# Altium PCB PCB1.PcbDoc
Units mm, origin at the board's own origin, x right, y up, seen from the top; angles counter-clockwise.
Board outline 116 x 60 mm, 4 copper layers (Top Layer, Inner up, Inner bottom, Bottom Layer), stack 0.602 mm thick; 2 components, 4 nets, 12 pads, 256 vias.
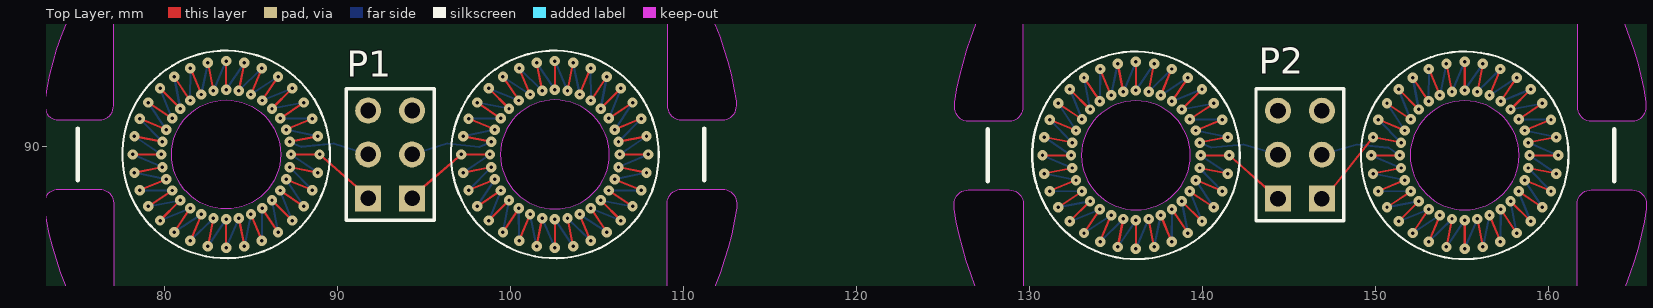
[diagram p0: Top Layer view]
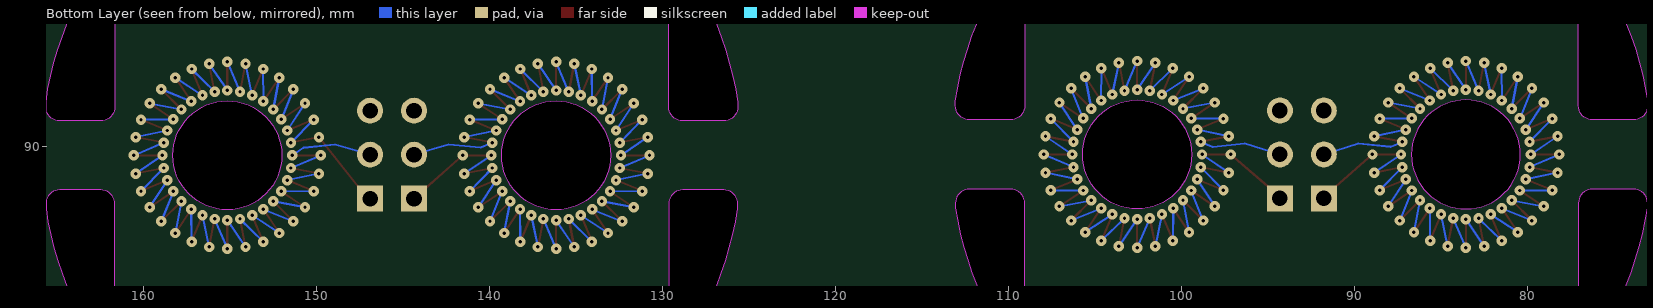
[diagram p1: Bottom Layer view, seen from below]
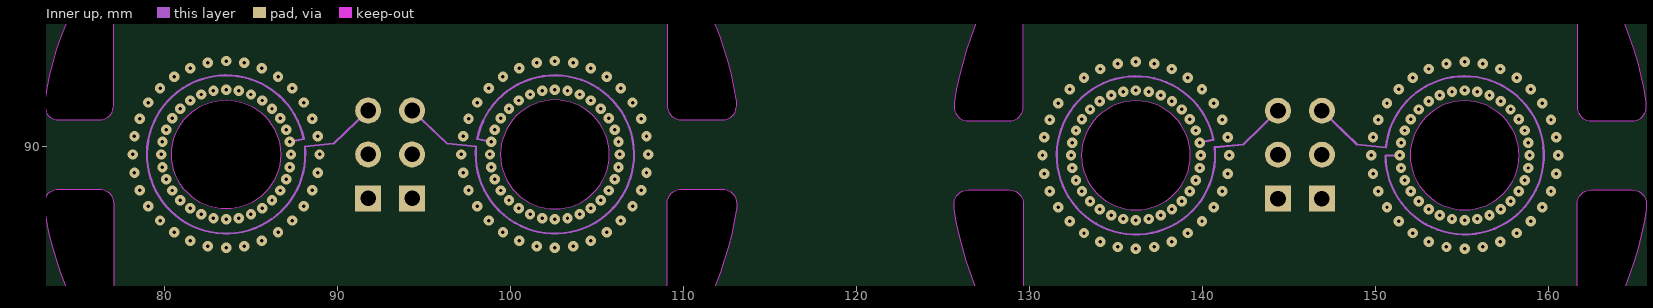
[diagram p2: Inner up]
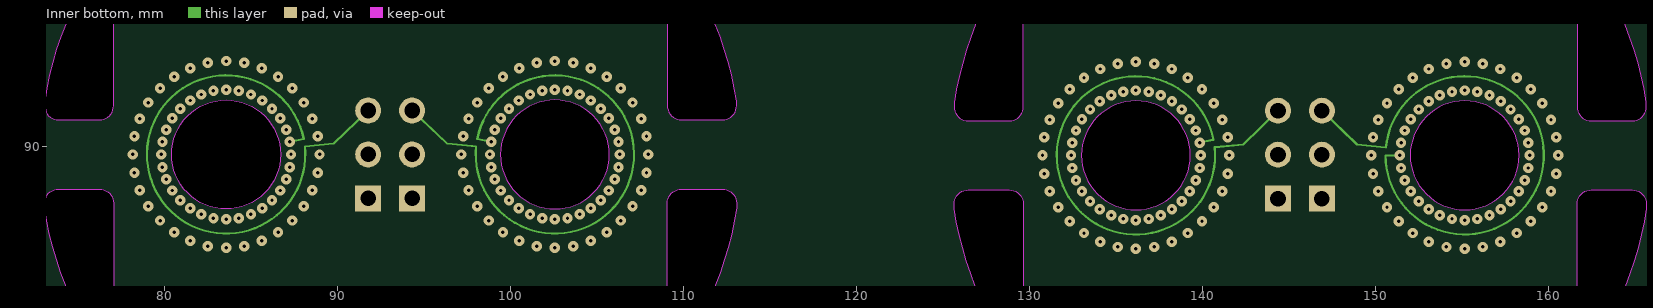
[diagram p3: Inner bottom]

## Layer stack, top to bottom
Top Solder: solder mask 0.0102, Solder Resist, Dk 3.5
Top Layer: signal copper 0.035
Dielectric 2: prepreg 0.0711, PP-006, Dk 4.1
Inner up: signal copper 0.035
Dielectric 1: dielectric 0.32, FR-4, Dk 4.8
Inner bottom: signal copper 0.035
Dielectric 3: prepreg 0.0711, PP-006, Dk 4.1
Bottom Layer: signal copper 0.035
Bottom Solder: solder mask 0.0102, Solder Resist, Dk 3.5

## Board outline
62,59 62,119 178,119 178,59
cut-out: 77.084,80.776 ccw(c93.084,89.555) 91.334,71.389 91.334,72.742 cw(c92.147,72.742) 92.147,73.555 94.021,73.555 cw(c94.021,72.742) 94.834,72.742 94.834,71.389 ccw(c93.084,89.555) 109.084,80.776 109.084,86.742 cw(c109.897,86.742) 109.897,87.555 112.275,87.555 cw(c112.275,86.742) 113.088,86.742 113.088,86.476 cw(c93.084,89.555) 73.08,86.482 73.08,86.742 cw(c73.893,86.742) 73.893,87.555 76.271,87.555 cw(c76.271,86.742) 77.084,86.742
cut-out: 73.078,92.368 ccw(c73.89,92.368) 73.89,91.555 76.271,91.555 ccw(c76.271,92.368) 77.084,92.368 77.084,98.334 cw(c93.084,89.555) 91.334,107.721 91.334,106.368 ccw(c92.147,106.368) 92.147,105.555 94.021,105.555 ccw(c94.021,106.368) 94.834,106.368 94.834,107.721 cw(c93.084,89.555) 109.084,98.334 109.084,92.368 ccw(c109.897,92.368) 109.897,91.555 112.276,91.555 ccw(c112.276,92.368) 113.089,92.368 113.089,92.629 ccw(c93.084,89.555) 73.078,92.614
cut-out: 125.661,92.317 ccw(c126.474,92.317) 126.474,91.504 128.855,91.504 ccw(c128.855,92.317) 129.667,92.317 129.667,98.283 cw(c145.667,89.504) 143.917,107.67 143.917,106.317 ccw(c144.73,106.317) 144.73,105.504 146.605,105.504 ccw(c146.605,106.317) 147.417,106.317 147.417,107.67 cw(c145.667,89.504) 161.667,98.283 161.667,92.317 ccw(c162.48,92.317) 162.48,91.504 164.859,91.504 ccw(c164.859,92.317) 165.672,92.317 165.672,92.578 ccw(c145.667,89.504) 125.661,92.564
cut-out: 129.667,80.726 ccw(c145.667,89.504) 143.917,71.338 143.917,72.691 cw(c144.73,72.691) 144.73,73.504 146.605,73.504 cw(c146.605,72.691) 147.417,72.691 147.417,71.338 ccw(c145.667,89.504) 161.667,80.726 161.667,86.691 cw(c162.48,86.691) 162.48,87.504 164.858,87.504 cw(c164.858,86.691) 165.671,86.691 165.671,86.426 cw(c145.667,89.504) 125.663,86.431 125.663,86.691 cw(c126.476,86.691) 126.476,87.504 128.855,87.504 cw(c128.855,86.691) 129.667,86.691
cut-out: 83.584,86.405 cw(c83.584,89.555) 80.434,89.555 cw(c83.584,89.555) 83.584,92.705 cw(c83.584,89.555) 86.734,89.555 cw(c83.584,89.555)
cut-out: 99.434,89.555 ccw(c102.584,89.555) 102.584,86.405 ccw(c102.584,89.555) 105.734,89.555 ccw(c102.584,89.555) 102.584,92.705 ccw(c102.584,89.555)
cut-out: 133.017,89.504 ccw(c136.167,89.504) 136.167,86.354 ccw(c136.167,89.504) 139.317,89.504 ccw(c136.167,89.504) 136.167,92.654 ccw(c136.167,89.504)
cut-out: 152.017,89.504 ccw(c155.167,89.504) 155.167,86.354 ccw(c155.167,89.504) 158.317,89.504 ccw(c155.167,89.504) 155.167,92.654 ccw(c155.167,89.504)

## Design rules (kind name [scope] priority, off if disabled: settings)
BoardOutlineClearance [All] p1: gap=0.2 ignorepadtopadclearanceinfootprint=FALSE
Clearance [All] p1: gap=0.102 ignorepadtopadclearanceinfootprint=FALSE except(0.127: Arc-Via Track-Via SMDPad-Via THPad-Via Via-Via Via-Fill Via-Poly Via-Region Via-Text; 0.25: Arc-Hole Track-Hole SMDPad-Hole THPad-Hole Via-Hole Fill-Hole Poly-Hole Region-Hole Text-Hole)
ComponentClearance [All] p1: gap=0.102 collisioncheckmode=3 verticalgap=0.102 showdistances=TRUE
DiffPairsRouting [All] p1: maxlimit=0.102 minlimit=0.102 mostfreqgap=0.102 toplayer_minwidth=0.102 toplayer_maxwidth=1816.048 toplayer_prefwidth=0.102 midlayer1_minwidth=0.102 midlayer1_maxwidth=1816.048 midlayer1_prefwidth=0.102 midlayer2_minwidth=0.102 midlayer2_maxwidth=1816.048 midlayer2_prefwidth=0.102 bottomlayer_minwidth=0.102 bottomlayer_maxwidth=1816.048 bottomlayer_prefwidth=0.102 maxuncoupledlength=12.7
Height [All] p1: minheight=0 maxheight=1816.048 prefheight=12.7
HoleSize [All] p1: absolutevalues=TRUE maxlimit=6.3 minlimit=0.2 maxpercent=80.000 minpercent=20.000
HoleToHoleClearance [All] p1: gap=0.25 allowstackedmicrovias=FALSE
MinimumAnnularRing [All] p1: minimumring=0.076
MinimumSolderMaskSliver [All] p1: minsoldermaskwidth=0
PlaneClearance [All] p1: clearance=0.102
PlaneConnect PlaneConnectPowerPads [InPadClass('PowerPads')] p1: planeconnectstyle=Direct reliefexpansion=0.508 reliefentries=4 reliefconductorwidth=0.254 reliefairgap=0.254
PlaneConnect [All] p2: pad.planeconnectstyle=Relief pad.reliefexpansion=0.3 pad.reliefentries=4 pad.reliefconductorwidth=0.102 pad.reliefairgap=0.102 via.planeconnectstyle=Direct via.reliefexpansion=0.3 via.reliefentries=4 via.reliefconductorwidth=0.127 via.reliefairgap=0.127
PolygonConnect PolygonConnectPowerPads [All vs (InPadClass('PowerPads'))] p1: connectstyle=Direct reliefconductorwidth=0.254 reliefentries=4 polygonreliefangle="90 Angle" airgapwidth=0.254
PolygonConnect [All] p2: thpad.connectstyle=Relief thpad.reliefconductorwidth=0.102 thpad.reliefentries=4 thpad.polygonreliefangle="90 Angle" thpad.airgapwidth=0.102 smdpad.connectstyle=Relief smdpad.reliefconductorwidth=0.102 smdpad.reliefentries=4 smdpad.polygonreliefangle="90 Angle" smdpad.airgapwidth=0.102 via.connectstyle=Direct via.reliefconductorwidth=0.127 via.reliefentries=4 via.polygonreliefangle="90 Angle" via.airgapwidth=0.127
RoutingVias [All] p1: holewidth=0.2 width=0.45 viastyle="Through Hole" minholewidth=0.2 minwidth=0.45 maxholewidth=6.3 maxwidth=6.55
SilkToSilkClearance [All] p1: silktosilkclearance=0
SilkToSolderMaskClearance [IsPad] p1: minsilkscreentomaskgap=0.102 clearancetoexposedcopper=TRUE
SolderMaskExpansion [All] p1: expansion=0.075 istentingtop=FALSE
Width [All] p1: maxlimit=1816.048 minlimit=0.102 preferedwidth=0.102
20 further rules are at their usual default settings.

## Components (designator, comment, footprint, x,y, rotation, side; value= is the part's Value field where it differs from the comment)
P1 "Header 3X2A" HDR2X3_CEN 94.334,87.015 r90 top
P2 "Header 3X2A" HDR2X3_CEN 146.917,87.004 r90 top

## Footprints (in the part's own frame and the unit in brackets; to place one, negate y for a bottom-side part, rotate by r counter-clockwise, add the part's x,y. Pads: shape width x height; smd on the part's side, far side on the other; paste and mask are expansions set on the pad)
HDR2X3_CEN [mm] "Connector; Header; 3x2 Position"
  rect 1.5x1.5 hole 0.9: 1(0,0) 4(0,2.54)
  round 1.5 hole 0.9: 2(2.54,0) 3(5.08,0) 5(2.54,2.54) 6(5.08,2.54)
  silkscreen extent -1.27,-1.27 6.35,3.81

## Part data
P1 P2: "Header, 3-Pin, Dual row"

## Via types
v1: diameter 0.6, hole 0.2, Top Layer to Bottom Layer, 256 vias

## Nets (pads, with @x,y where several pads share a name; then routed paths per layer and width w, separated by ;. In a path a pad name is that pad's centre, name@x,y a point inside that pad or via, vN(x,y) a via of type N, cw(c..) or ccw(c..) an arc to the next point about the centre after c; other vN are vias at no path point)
coil1: P2.1 P2.2 P2.3 | length 187.4
  Top Layer w0.125: P2.1 147.605,87.692 v1(149.871,90.558) v1(151.489,90.236) ; v1(149.767,89.504) v1(151.417,89.504) ; v1(149.871,88.451) v1(151.489,88.773) ; v1(150.178,87.438) v1(151.703,88.069) ; v1(150.178,91.571) v1(151.703,90.939) ; v1(150.677,86.504) v1(152.049,87.421) ; v1(150.677,92.504) v1(152.049,91.588) ; v1(151.349,85.686) v1(152.516,86.853) ; v1(151.349,93.323) v1(152.516,92.156) ; v1(152.167,85.014) v1(153.084,86.386) ; v1(152.167,93.994) v1(153.084,92.622) ; v1(153.101,84.515) v1(153.732,86.04) ; v1(153.101,94.493) v1(153.732,92.969) ; v1(154.114,84.208) v1(154.436,85.826) ; v1(154.114,94.8) v1(154.436,93.182) ; v1(155.167,84.104) v1(155.167,85.754) ; v1(155.167,93.254) v1(155.167,94.904) ; v1(155.899,85.826) v1(156.221,84.208) ; v1(155.899,93.182) v1(156.221,94.8) ; v1(156.602,86.04) v1(157.234,84.515) ; v1(156.602,92.969) v1(157.234,94.493) ; v1(157.251,86.386) v1(158.167,85.014) ; v1(157.251,92.622) v1(158.167,93.994) ; v1(157.819,86.853) v1(158.986,85.686) ; v1(157.819,92.156) v1(158.986,93.323) ; v1(158.285,87.421) v1(159.657,86.504) ; v1(158.285,91.588) v1(159.657,92.504) ; v1(158.632,88.069) v1(160.156,87.438) ; v1(158.632,90.939) v1(160.156,91.571) ; v1(158.845,88.773) v1(160.464,88.451) ; v1(158.845,90.236) v1(160.464,90.558) ; v1(158.917,89.504) v1(160.567,89.504)
  Inner up w0.125: P2.3 148.942,90.129 150.615,89.961 cw(c155.167,89.504) 150.592,89.504 v1(151.417,89.504)
  Inner bottom w0.125: P2.3 148.942,90.129 150.615,89.961 cw(c155.167,89.504) 150.592,89.504 v1(151.417,89.504)
  Bottom Layer w0.125: P2.2 148.942,90.129 150.769,89.946 v1(151.417,89.504) ; v1(149.767,89.504) v1(151.489,88.773) ; v1(149.871,88.451) v1(151.703,88.069) ; v1(150.178,87.438) v1(152.049,87.421) ; v1(150.178,91.571) v1(151.489,90.236) ; v1(150.677,86.504) v1(152.516,86.853) ; v1(150.677,92.504) v1(151.703,90.939) ; v1(151.349,85.686) v1(153.084,86.386) ; v1(151.349,93.323) v1(152.049,91.588) ; v1(152.167,85.014) v1(153.732,86.04) ; v1(152.167,93.994) v1(152.516,92.156) ; v1(153.084,92.622) v1(153.101,94.493) ; v1(153.101,84.515) v1(154.436,85.826) ; v1(153.732,92.969) v1(154.114,94.8) ; v1(154.114,84.208) v1(155.167,85.754) ; v1(154.436,93.182) v1(155.167,94.904) ; v1(155.167,84.104) v1(155.899,85.826) ; v1(155.167,93.254) v1(156.221,94.8) ; v1(155.899,93.182) v1(157.234,94.493) ; v1(156.221,84.208) v1(156.602,86.04) ; v1(156.602,92.969) v1(158.167,93.994) ; v1(157.234,84.515) v1(157.251,86.386) ; v1(157.251,92.622) v1(158.986,93.323) ; v1(157.819,86.853) v1(158.167,85.014) ; v1(157.819,92.156) v1(159.657,92.504) ; v1(158.285,87.421) v1(158.986,85.686) ; v1(158.285,91.588) v1(160.156,91.571) ; v1(158.632,88.069) v1(159.657,86.504) ; v1(158.632,90.939) v1(160.464,90.558) ; v1(158.845,88.773) v1(160.156,87.438) ; v1(158.845,90.236) v1(160.567,89.504) ; v1(158.917,89.504) v1(160.464,88.451)
coil2: P2.4 P2.5 P2.6 | length 186.4
  Top Layer w0.125: v1(130.767,89.504) v1(132.417,89.504) ; v1(130.871,88.451) v1(132.489,88.773) ; v1(130.871,90.558) v1(132.489,90.236) ; v1(131.178,87.438) v1(132.703,88.069) ; v1(131.178,91.571) v1(132.703,90.939) ; v1(131.677,86.504) v1(133.049,87.421) ; v1(131.677,92.504) v1(133.049,91.588) ; v1(132.349,85.686) v1(133.516,86.853) ; v1(132.349,93.323) v1(133.516,92.156) ; v1(133.167,85.014) v1(134.084,86.386) ; v1(133.167,93.994) v1(134.084,92.622) ; v1(134.101,84.515) v1(134.732,86.04) ; v1(134.101,94.493) v1(134.732,92.969) ; v1(135.114,84.208) v1(135.436,85.826) ; v1(135.114,94.8) v1(135.436,93.182) ; v1(136.167,84.104) v1(136.167,85.754) ; v1(136.167,93.254) v1(136.167,94.904) ; v1(136.899,85.826) v1(137.221,84.208) ; v1(136.899,93.182) v1(137.221,94.8) ; v1(137.602,86.04) v1(138.234,84.515) ; v1(137.602,92.969) v1(138.234,94.493) ; v1(138.251,86.386) v1(139.167,85.014) ; v1(138.251,92.622) v1(139.167,93.994) ; v1(138.819,86.853) v1(139.986,85.686) ; v1(138.819,92.156) v1(139.986,93.323) ; v1(139.285,87.421) v1(140.657,86.504) ; v1(139.285,91.588) v1(140.657,92.504) ; v1(139.632,88.069) v1(141.156,87.438) ; v1(139.632,90.939) v1(141.156,91.571) ; v1(139.845,88.773) v1(141.464,88.451) ; v1(139.845,90.236) v1(141.464,90.558) ; v1(139.917,89.504) v1(141.567,89.504) P2.4
  Inner up w0.125: v1(139.845,90.236) 140.654,90.401 ccw(c136.167,89.504) 140.719,89.967 142.386,90.137 P2.6
  Inner bottom w0.125: v1(139.845,90.236) 140.654,90.401 ccw(c136.167,89.504) 140.719,89.967 142.386,90.137 P2.6
  Bottom Layer w0.125: v1(130.767,89.504) v1(132.489,88.773) ; v1(130.871,88.451) v1(132.703,88.069) ; v1(130.871,90.558) v1(132.417,89.504) ; v1(131.178,87.438) v1(133.049,87.421) ; v1(131.178,91.571) v1(132.489,90.236) ; v1(131.677,86.504) v1(133.516,86.853) ; v1(131.677,92.504) v1(132.703,90.939) ; v1(132.349,85.686) v1(134.084,86.386) ; v1(132.349,93.323) v1(133.049,91.588) ; v1(133.167,85.014) v1(134.732,86.04) ; v1(133.167,93.994) v1(133.516,92.156) ; v1(134.084,92.622) v1(134.101,94.493) ; v1(134.101,84.515) v1(135.436,85.826) ; v1(134.732,92.969) v1(135.114,94.8) ; v1(135.114,84.208) v1(136.167,85.754) ; v1(135.436,93.182) v1(136.167,94.904) ; v1(136.167,84.104) v1(136.899,85.826) ; v1(136.167,93.254) v1(137.221,94.8) ; v1(136.899,93.182) v1(138.234,94.493) ; v1(137.221,84.208) v1(137.602,86.04) ; v1(137.602,92.969) v1(139.167,93.994) ; v1(138.234,84.515) v1(138.251,86.386) ; v1(138.251,92.622) v1(139.986,93.323) ; v1(138.819,86.853) v1(139.167,85.014) ; v1(138.819,92.156) v1(140.657,92.504) ; v1(139.285,87.421) v1(139.986,85.686) ; v1(139.285,91.588) v1(141.156,91.571) ; v1(139.632,88.069) v1(140.657,86.504) ; v1(139.632,90.939) v1(141.464,90.558) ; v1(139.845,88.773) v1(141.156,87.438) ; v1(139.845,90.236) 140.524,89.948 142.386,90.137 P2.5 ; v1(139.917,89.504) v1(141.464,88.451)
coil3: P1.1 P1.2 P1.3 | length 188
  Top Layer w0.125: P1.1 95.022,87.703 v1(97.184,89.555) v1(98.834,89.555) ; v1(97.288,88.502) v1(98.906,88.823) ; v1(97.288,90.608) v1(98.906,90.287) ; v1(97.595,87.489) v1(99.12,88.12) ; v1(97.595,91.621) v1(99.12,90.99) ; v1(98.094,86.555) v1(99.466,87.472) ; v1(98.094,92.555) v1(99.466,91.638) ; v1(98.766,85.737) v1(99.933,86.903) ; v1(98.766,93.373) v1(99.933,92.207) ; v1(99.584,85.065) v1(100.501,86.437) ; v1(99.584,94.045) v1(100.501,92.673) ; v1(100.518,84.566) v1(101.149,86.09) ; v1(100.518,94.544) v1(101.149,93.02) ; v1(101.531,84.259) v1(101.853,85.877) ; v1(101.531,94.851) v1(101.853,93.233) ; v1(102.584,84.155) v1(102.584,85.805) ; v1(102.584,93.305) v1(102.584,94.955) ; v1(103.316,85.877) v1(103.638,84.259) ; v1(103.316,93.233) v1(103.638,94.851) ; v1(104.019,86.09) v1(104.651,84.566) ; v1(104.019,93.02) v1(104.651,94.544) ; v1(104.668,86.437) v1(105.584,85.065) ; v1(104.668,92.673) v1(105.584,94.045) ; v1(105.236,86.903) v1(106.403,85.737) ; v1(105.236,92.207) v1(106.403,93.373) ; v1(105.702,87.472) v1(107.074,86.555) ; v1(105.702,91.638) v1(107.074,92.555) ; v1(106.049,88.12) v1(107.573,87.489) ; v1(106.049,90.99) v1(107.573,91.621) ; v1(106.262,88.823) v1(107.88,88.502) ; v1(106.262,90.287) v1(107.88,90.608) ; v1(106.334,89.555) v1(107.984,89.555)
  Inner up w0.125: P1.3 96.359,90.18 98.032,90.013 ccw(c102.584,89.555) 98.097,90.448 v1(98.906,90.287)
  Inner bottom w0.125: P1.3 96.359,90.18 ; 97.81,90.034 96.359,90.18 ; v1(98.906,90.287) 98.097,90.448 cw(c102.584,89.555) 98.032,90.013 96.359,90.18
  Bottom Layer w0.125: P1.2 96.362,90.18 98.216,89.994 v1(98.906,90.287) ; v1(97.288,88.502) v1(98.834,89.555) ; v1(97.288,90.608) v1(99.12,90.99) ; v1(97.595,87.489) v1(98.906,88.823) ; v1(97.595,91.621) v1(99.466,91.638) ; v1(98.094,86.555) v1(99.12,88.12) ; v1(98.094,92.555) v1(99.933,92.207) ; v1(98.766,85.737) v1(99.466,87.472) ; v1(98.766,93.373) v1(100.501,92.673) ; v1(99.584,85.065) v1(99.933,86.903) ; v1(99.584,94.045) v1(101.149,93.02) ; v1(100.501,86.437) v1(100.518,84.566) ; v1(100.518,94.544) v1(101.853,93.233) ; v1(101.149,86.09) v1(101.531,84.259) ; v1(101.531,94.851) v1(102.584,93.305) ; v1(101.853,85.877) v1(102.584,84.155) ; v1(102.584,85.805) v1(103.638,84.259) ; v1(102.584,94.955) v1(103.316,93.233) ; v1(103.316,85.877) v1(104.651,84.566) ; v1(103.638,94.851) v1(104.019,93.02) ; v1(104.019,86.09) v1(105.584,85.065) ; v1(104.651,94.544) v1(104.668,92.673) ; v1(104.668,86.437) v1(106.403,85.737) ; v1(105.236,86.903) v1(107.074,86.555) ; v1(105.236,92.207) v1(105.584,94.045) ; v1(105.702,87.472) v1(107.573,87.489) ; v1(105.702,91.638) v1(106.403,93.373) ; v1(106.049,88.12) v1(107.88,88.502) ; v1(106.049,90.99) v1(107.074,92.555) ; v1(106.262,88.823) v1(107.984,89.555) ; v1(106.262,90.287) v1(107.573,91.621) ; v1(106.334,89.555) v1(107.88,90.608)
coil4: P1.4 P1.5 P1.6 | length 186.4
  Top Layer w0.125: v1(78.184,89.555) v1(79.834,89.555) ; v1(78.288,88.502) v1(79.906,88.823) ; v1(78.288,90.608) v1(79.906,90.287) ; v1(78.595,87.489) v1(80.12,88.12) ; v1(78.595,91.621) v1(80.12,90.99) ; v1(79.094,86.555) v1(80.466,87.472) ; v1(79.094,92.555) v1(80.466,91.638) ; v1(79.766,85.737) v1(80.933,86.903) ; v1(79.766,93.373) v1(80.933,92.207) ; v1(80.584,85.065) v1(81.501,86.437) ; v1(80.584,94.045) v1(81.501,92.673) ; v1(81.518,84.566) v1(82.149,86.09) ; v1(81.518,94.544) v1(82.149,93.02) ; v1(82.531,84.259) v1(82.853,85.877) ; v1(82.531,94.851) v1(82.853,93.233) ; v1(83.584,84.155) v1(83.584,85.805) ; v1(83.584,93.305) v1(83.584,94.955) ; v1(84.316,85.877) v1(84.638,84.259) ; v1(84.316,93.233) v1(84.638,94.851) ; v1(85.019,86.09) v1(85.651,84.566) ; v1(85.019,93.02) v1(85.651,94.544) ; v1(85.668,86.437) v1(86.584,85.065) ; v1(85.668,92.673) v1(86.584,94.045) ; v1(86.236,86.903) v1(87.403,85.737) ; v1(86.236,92.207) v1(87.403,93.373) ; v1(86.702,87.472) v1(88.074,86.555) ; v1(86.702,91.638) v1(88.074,92.555) ; v1(87.049,88.12) v1(88.573,87.489) ; v1(87.049,90.99) v1(88.573,91.621) ; v1(87.262,88.823) v1(88.88,88.502) ; v1(87.262,90.287) v1(88.88,90.608) ; v1(87.334,89.555) v1(88.984,89.555) 91.107,87.703 P1.4
  Inner up w0.125: v1(87.262,90.287) 88.07,90.452 ccw(c83.584,89.555) 88.136,90.018 89.803,90.188 P1.6
  Inner bottom w0.125: v1(87.262,90.287) 88.07,90.452 ccw(c83.584,89.555) 88.136,90.018 89.803,90.188 P1.6
  Bottom Layer w0.125: v1(78.184,89.555) v1(79.906,88.823) ; v1(78.288,88.502) v1(80.12,88.12) ; v1(78.288,90.608) v1(79.834,89.555) ; v1(78.595,87.489) v1(80.466,87.472) ; v1(78.595,91.621) v1(79.906,90.287) ; v1(79.094,86.555) v1(80.933,86.903) ; v1(79.094,92.555) v1(80.12,90.99) ; v1(79.766,85.737) v1(81.501,86.437) ; v1(79.766,93.373) v1(80.466,91.638) ; v1(80.584,85.065) v1(82.149,86.09) ; v1(80.584,94.045) v1(80.933,92.207) ; v1(81.501,92.673) v1(81.518,94.544) ; v1(81.518,84.566) v1(82.853,85.877) ; v1(82.149,93.02) v1(82.531,94.851) ; v1(82.531,84.259) v1(83.584,85.805) ; v1(82.853,93.233) v1(83.584,94.955) ; v1(83.584,84.155) v1(84.316,85.877) ; v1(83.584,93.305) v1(84.638,94.851) ; v1(84.316,93.233) v1(85.651,94.544) ; v1(84.638,84.259) v1(85.019,86.09) ; v1(85.019,93.02) v1(86.584,94.045) ; v1(85.651,84.566) v1(85.668,86.437) ; v1(85.668,92.673) v1(87.403,93.373) ; v1(86.236,86.903) v1(86.584,85.065) ; v1(86.236,92.207) v1(88.074,92.555) ; v1(86.702,87.472) v1(87.403,85.737) ; v1(86.702,91.638) v1(88.573,91.621) ; v1(87.049,88.12) v1(88.074,86.555) ; v1(87.049,90.99) v1(88.88,90.608) ; v1(87.262,88.823) v1(88.573,87.489) ; v1(87.262,90.287) 87.941,89.998 89.803,90.188 P1.5 ; v1(87.334,89.555) v1(88.88,88.502)

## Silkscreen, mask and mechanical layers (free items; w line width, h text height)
Top Overlay:
  circle w0.125: c102.584,89.555 r6
  circle w0.125: c83.584,89.555 r6
  circle w0.125: c136.167,89.504 r6
  circle w0.125: c155.167,89.504 r6
  lines w0.254: 75.014,88.055 75.014,89.555 75.014,91.055 ; 111.224,88.055 111.224,89.555 111.224,91.055 ; 127.597,88.004 127.597,89.504 127.597,91.004 ; 163.807,88.004 163.807,89.504 163.807,91.004
Mechanical 1:
  circle w0.125: c102.584,89.555 r3.15
  circle w0.125: c83.584,89.555 r3.15
  circle w0.125: c136.167,89.504 r3.15
  circle w0.125: c155.167,89.504 r3.15
  lines w0.05: 147.417,71.338 ccw(c147.417,71.338) 147.417,71.338
  lines w0.254: 147.417,71.338 ccw(c147.417,71.338) 147.417,71.338 ; 147.417,71.338 ccw(c147.417,71.338) 147.417,71.338 ; 147.417,71.338 ccw(c145.667,89.504) 161.667,80.726 161.667,86.691 cw(c162.48,86.691) 162.48,87.504 163.737,87.504 164.858,87.504 cw(c164.858,86.691) 165.671,86.691 165.671,86.426 cw(c145.667,89.504) 125.663,86.431 125.663,86.691 cw(c126.476,86.691) 126.476,87.504 127.597,87.504 128.855,87.504 cw(c128.855,86.691) 129.667,86.691 129.667,80.726 ccw(c145.667,89.504) 143.917,71.338 143.917,72.691 cw(c144.73,72.691) 144.73,73.504 146.605,73.504 cw(c146.605,72.691) 147.417,72.691 147.417,71.338 ; 147.417,107.67 ccw(c147.417,107.67) 147.417,107.67 ; 147.417,107.67 cw(c145.667,89.504) 161.667,98.283 161.667,92.317 ccw(c162.48,92.317) 162.48,91.504 163.807,91.504 164.859,91.504 ccw(c164.859,92.317) 165.672,92.317 165.672,92.578 ccw(c145.667,89.504) 125.661,92.564 125.661,92.317 ccw(c126.474,92.317) 126.474,91.504 127.597,91.504 128.855,91.504 ccw(c128.855,92.317) 129.667,92.317 129.667,98.283 cw(c145.667,89.504) 143.917,107.67 143.917,106.317 ccw(c144.73,106.317) 144.73,105.504 146.605,105.504 ccw(c146.605,106.317) 147.417,106.317 147.417,107.67 ; 62,59 178,59 178,119 62,119 62,59 ; 73.078,92.368 ccw(c73.89,92.368) 73.89,91.555 75.014,91.555 76.271,91.555 ccw(c76.271,92.368) 77.084,92.368 77.084,98.334 cw(c93.084,89.555) 91.334,107.721 91.334,106.368 ccw(c92.147,106.368) 92.147,105.555 94.021,105.555 ccw(c94.021,106.368) 94.834,106.368 94.834,107.721 cw(c93.084,89.555) 109.084,98.334 109.084,92.368 ccw(c109.897,92.368) 109.897,91.555 111.224,91.555 112.276,91.555 ccw(c112.276,92.368) 113.089,92.368 113.089,92.629 ccw(c93.084,89.555) 73.078,92.614 73.078,92.368 ; 73.08,86.482 ccw(c93.084,89.555) 113.088,86.476 113.088,86.742 ccw(c112.275,86.742) 112.275,87.555 111.154,87.555 109.897,87.555 ccw(c109.897,86.742) 109.084,86.742 109.084,80.776 cw(c93.084,89.555) 94.834,71.389 94.834,72.742 ccw(c94.021,72.742) 94.021,73.555 92.147,73.555 ccw(c92.147,72.742) 91.334,72.742 91.334,71.389 cw(c93.084,89.555) 77.084,80.776 77.084,86.742 ccw(c76.271,86.742) 76.271,87.555 75.014,87.555 73.893,87.555 ccw(c73.893,86.742) 73.08,86.742 73.08,86.482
